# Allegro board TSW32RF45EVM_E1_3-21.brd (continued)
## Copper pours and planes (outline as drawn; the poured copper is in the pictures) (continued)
N19887910 on TOP: 88.44,56.29 88.44,55.02 90.4,55.02 90.4,56.29
N19887912 on TOP: 88.21,54.38 88.21,53.16 90.3,53.16 90.3,54.38
N19887930 on TOP: 88.47,58.55 88.47,57.28 90.42,57.28 90.42,58.55
N20113513 on BOTTOM: 87.55,9.17 87.55,11.07 88.57,11.07 88.57,13.49 94.67,13.49 94.67,11.71 92.13,9.17
N20114896 on TOP: 99.72,15.82 99.72,9.47 103.66,9.47 103.66,15.82
N20114896 on BOTTOM: 98.07,5.66 98.07,14.55 99.34,15.82 103.28,15.82 103.66,15.44 103.66,6.55 101.75,4.65 99.09,4.65
N20121078 on BOTTOM: 93.01,14.25 93.01,16.03 92.13,16.92 88.7,16.92 88.7,18.95 93.4,18.95 95.3,17.04 95.3,14.25

Small or netless copper shapes (teardrops, artwork), in the pictures only: 2 on TOP

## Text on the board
BOTTOM: LAYER 8 (BOTTOM SIDE)
Board Geometry/Soldermask Bottom: SOLDERMASK BOTTOM
Ref Des/Silkscreen Bottom: SILKSCREEN BOTTOM
User.Comments: INSTALL HEATSINK HS1 | ON BOTTOM SIDE OF BOARD | TEXAS INSTRUMENTS, INC. | PCB REV E1 | TSW32RF45EVM HSP-013 | 8MIL TRACE WIDTH AND 6MIL SPACING ON BOTTOM SIDE OF BOARD SHALL BE 100 OHMS DIFFERENTIAL +/- 10%. | TOP VIEW | BOTTOM VIEW
TOP: LAYER 1 (TOP SIDE)
Board Geometry/Soldermask Top: SOLDERMASK TOP
Ref Des/Silkscreen Top: CLK | EXT | ADC CLK IN | J5 | LMK SYNC | BINM | BINP | AINP | AINM | GND | LOCKED | TSW32RF45EVM HSP-013 REV E1 | SILKSCREEN TOP
L2_GND: LAYER 2 - GND
L3_PWR: LAYER 3 - POWER
L4_SIG: LAYER 4 - GND
L5_GND: LAYER 5 - GND
L6_PWR: LAYER 6 - POWER/SIGNAL
L7_GND: LAYER 7 - GROUND
PLACE_BOUND_TOP: PASTEMASK TOP
DEVICE_TYPE_BOTTOM: PASTEMASK BOTTOM
USER_PART_NUM_BOTTOM: SOLDERMASK TOP SOCKET BOARD
PAGE_OUTLINE: PASTEMASK TOP SOCKET BOARD
User.11: 0.25oz / Plate to 0.5oz min Layer 6 | R-1775V | R-1650V | Core 0.008" | Copper Foil | Core 0.012" | Pre-preg 0.0042 | 0.5oz / 0.5oz Layer 5 & 6 | (material) | LAYER 7 | LAYER 8
User.12: 03-18-16 | 4. IPC-A-610 / ACCEPTABILITY OF ELECTRONIC ASSEMBLIES, CLASS2, CURRENT REVISION. | 3. ATTACH HEAT SINK USING THERMALLY CONDUCTIVE GLUE.
User.21: FIGURE | SIZE | 6.0 | 8.0 | 10.0 | 12.0 | 13.0 | 15.0 | 38.0 | 40.0 | 62.0 | 67.0 | 106.0 | 120.0 | 125.0 | 140.0 | 35.0 | 50.0 | DRILL CHART: TOP to BOTTOM | ALL UNITS ARE IN MILS | PLATED | NON-PLATED | QTY | 175 | 2207 | 139 | 511 | 16 | 8 | 12 | 20 | 5 | 2 | 1
User.25: HS1 | R72 | R80 | C81 | C84 | R54 | C170 | C171 | R53 | C71 | C85 | C82 | R52 | R51 | R50 | R70 | R67 | R69 | R68 | C74 | C73 | R63 | R47 | C70 | R64 | T6 | R56 | R57 | C412 | R177 | C413 | R184 | C60 | C59 | C58 | C28 | R75 | R79 | R81 | R73 | R71 | R76 | R74 | R82 | C72 | R152 | C67 | C83 | C86 | C69 | R48 | R49 | R180 | C419 | C418 | R181 | R65 | R66 | C8 | C9 | C75 | R55 | R60 | R85 | R59 | R191 | R84 | R58 | R87 | R86 | R192 | R178 | R187 | R32 | R34 | R31 | C47 | C38 | C45 | C44 | C39 | R151 | R77 | R78 | R40 | Y1 | U13 | C76 | C62 | C63 | U4 | C65 | C64 | C100 | C66 | C157 | C158 | U12 | C162 | C163 | C160 | C161 | C159 | C385 | C388 | C389 | U9 | R158 | U3 | R145 | U17 | R159 | C198 | R157 | R139 | R140 | R141 | R138 | R174 | C394 | U16 | R137 | R186 | C191 | C190 | C189 | C421 | C188 | C187 | C186 | C185 | U10 | R133 | R185 | R179 | C400 | R175 | R176 | U15 | C409 | C410 | U5 | R188 | C25 | C29 | C32 | C34 | C1 | C114 | T5 | J11 | FB13 | C12 | C11 | C35 | FB16 | C156 | C386 | FB17 | C193 | C197 | R143 | C194 | R35 | C195 | C196 | R33 | C122 | C126 | C395 | R182 | C403 | C420 | R183 | C173 | C431 | C432 | F1 | R189 | C428 | R95 | FB12 | C104 | C103 | * | R165 | R164 | J5 | J10
